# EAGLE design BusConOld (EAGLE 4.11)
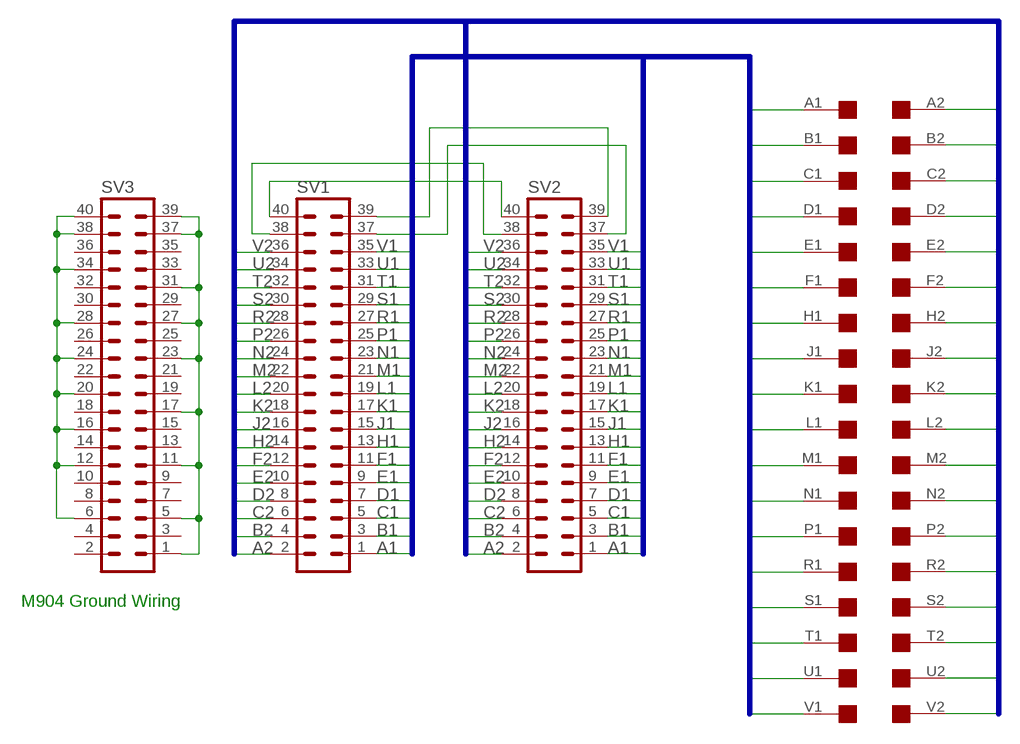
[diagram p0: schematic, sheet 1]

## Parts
SV1  MA20-2W  [MA20-2W]
SV2  MA20-2W  [MA20-2W]
SV3  MA20-2W  [MA20-2W]
U$1  DEC-FLIPCHIP  [DEC-FLIPCHIP]

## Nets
A1: SV1.1 SV2.1 U$1.A1
A2: SV1.2 SV2.2 U$1.A2
B1: SV1.3 SV2.3 U$1.B1
B2: SV1.4 SV2.4 U$1.B2
C1: SV1.5 SV2.5 U$1.C1
C2: SV1.6 SV2.6 U$1.C2
D1: SV1.7 SV2.7 U$1.D1
D2: SV1.8 SV2.8 U$1.D2
E1: SV1.9 SV2.9 U$1.E1
E2: SV1.10 SV2.10 U$1.E2
F1: SV1.11 SV2.11 U$1.F1
F2: SV1.12 SV2.12 U$1.F2
H1: SV1.13 SV2.13 U$1.H1
H2: SV1.14 SV2.14 U$1.H2
J1: SV1.15 SV2.15 U$1.J1
J2: SV1.16 SV2.16 U$1.J2
K1: SV1.17 SV2.17 U$1.K1
K2: SV1.18 SV2.18 U$1.K2
L1: SV1.19 SV2.19 U$1.L1
L2: SV1.20 SV2.20 U$1.L2
M1: SV1.21 SV2.21 U$1.M1
M2: SV1.22 SV2.22 U$1.M2
N1: SV1.23 SV2.23 U$1.N1
N2: SV1.24 SV2.24 U$1.N2
N$1: SV1.40 SV2.40
N$2: SV1.38 SV2.38
N$3: SV1.37 SV2.37
N$4: SV1.39 SV2.39
N$5: SV3.1 SV3.5 SV3.11 SV3.17 SV3.23 SV3.27 SV3.31 SV3.37 SV3.39
N$6: SV3.6 SV3.12 SV3.16 SV3.20 SV3.24 SV3.28 SV3.34 SV3.38 SV3.40
P1: SV1.25 SV2.25 U$1.P1
P2: SV1.26 SV2.26 U$1.P2
R1: SV1.27 SV2.27 U$1.R1
R2: SV1.28 SV2.28 U$1.R2
S1: SV1.29 SV2.29 U$1.S1
S2: SV1.30 SV2.30 U$1.S2
T1: SV1.31 SV2.31 U$1.T1
T2: SV1.32 SV2.32 U$1.T2
U1: SV1.33 SV2.33 U$1.U1
U2: SV1.34 SV2.34 U$1.U2
V1: SV1.35 SV2.35 U$1.V1
V2: SV1.36 SV2.36 U$1.V2
Unconnected: SV3.2 SV3.3 SV3.4 SV3.7 SV3.8 SV3.9 SV3.10 SV3.13 SV3.14 SV3.15 SV3.18 SV3.19 SV3.21 SV3.22 SV3.25 SV3.26 SV3.29 SV3.30 SV3.32 SV3.33 SV3.35 SV3.36

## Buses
A1,B1,C1,D1,E1,F1,H1,J1,K1,L1,M1,N1,P1,R1,S1,T1,U1,V1
A2,B2,C2,D2,E2,F2,H2,J2,K2,L2,M2,N2,P2,R2,S2,T2,U2,V2

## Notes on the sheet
- M904 Ground Wiring

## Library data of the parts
SV1-SV3 = con-lstb:MA20-2W: PIN HEADER
U$1 = con-dec:DEC-FLIPCHIP: DEC Flip-Chip single card fingers

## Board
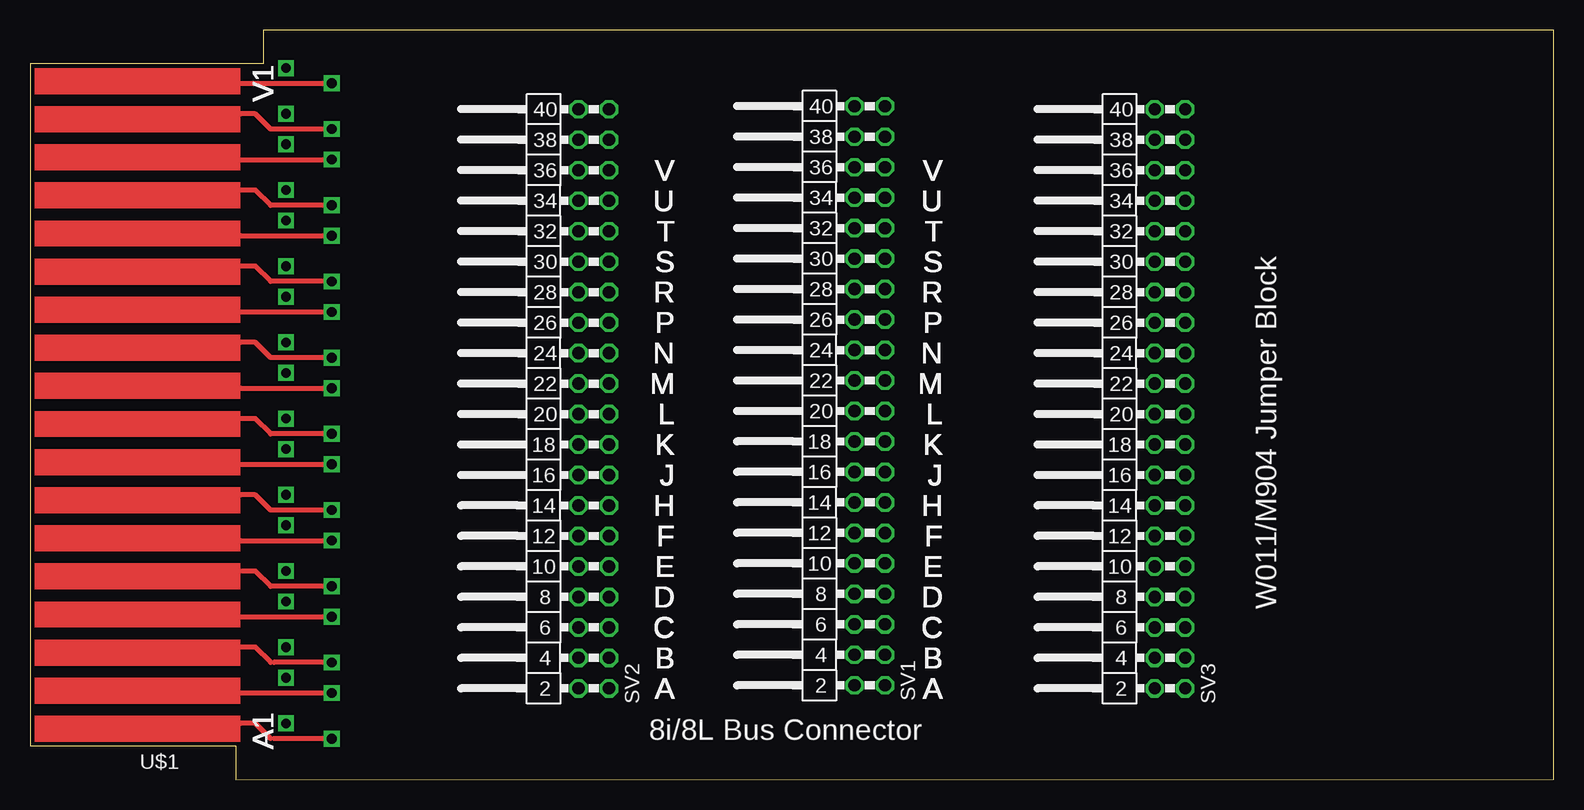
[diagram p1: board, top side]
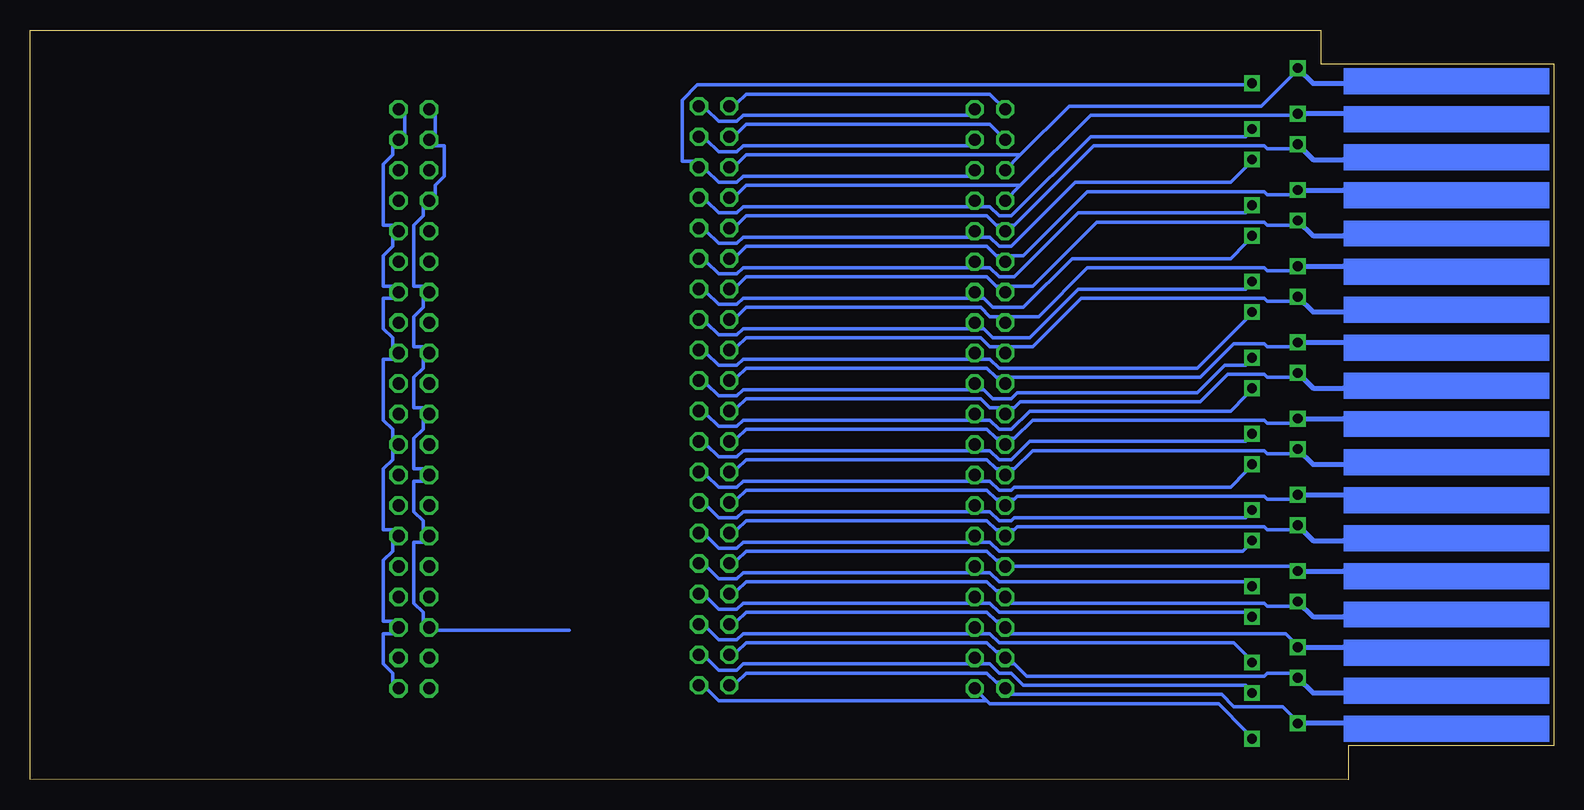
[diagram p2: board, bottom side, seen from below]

Size 126.98 x 62.48 mm. Coordinates in mm from the lower left corner, seen from the top.
Outline: 0,2.83 17.14,2.83 17.14,0 126.98,0.04 126.98,62.45 19.43,62.48 19.43,59.65 0,59.65 0,2.83
Copper layers (1*16): Top 0.035mm / dielectric 1.5mm / Bottom 0.035mm
Design rules "10mils": minimum track width 12mil, minimum drill 28mil, track to track 10mil, track to pad 10mil, pad to pad 10mil, via to via 10mil, smd to smd 10mil, copper to edge 40mil, drill to drill 10mil, minimum pad ring 10mil, minimum via ring 8mil, stop-mask expansion 0mil, vias tented up to drill 0mil, thermal gap 10mil

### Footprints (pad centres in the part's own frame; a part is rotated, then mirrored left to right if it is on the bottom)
MA20-2W = drill 1.016 octagon: 1 -24.13,-1.27; 2 -24.13,1.27; 3 -21.59,-1.27; 4 -21.59,1.27; 5 -19.05,-1.27; 6 -19.05,1.27; 7 -16.51,-1.27; 8 -16.51,1.27; 9 -13.97,-1.27; 10 -13.97,1.27; 11 -11.43,-1.27; 12 -11.43,1.27; 13 -8.89,-1.27; 14 -8.89,1.27; 15 -6.35,-1.27; 16 -6.35,1.27; 17 -3.81,-1.27; 18 -3.81,1.27; 19 -1.27,-1.27; 20 -1.27,1.27; 21 1.27,-1.27; 22 1.27,1.27; 23 3.81,-1.27; 24 3.81,1.27; 25 6.35,-1.27; 26 6.35,1.27; 27 8.89,-1.27; 28 8.89,1.27; 29 11.43,-1.27; 30 11.43,1.27; 31 13.97,-1.27; 32 13.97,1.27; 33 16.51,-1.27; 34 16.51,1.27; 35 19.05,-1.27; 36 19.05,1.27; 37 21.59,-1.27; 38 21.59,1.27; 39 24.13,-1.27; 40 24.13,1.27
DEC-FLIPCHIP = drill 0.813 square: A1 -7.62,27.94; A2 -3.81,26.67; B1 -7.62,24.13; B2 -3.81,22.86; C1 -7.62,21.59; C2 -3.81,20.32; D1 -7.62,17.78; D2 -3.81,16.51; E1 -7.62,15.24; E2 -3.81,13.97; F1 -7.62,11.43; F2 -3.81,10.16; H1 -7.62,8.89; H2 -3.81,7.62; J1 -7.62,5.08; J2 -3.81,3.81; K1 -7.62,2.54; K2 -3.81,1.27; L1 -7.62,-1.27; L2 -3.81,-2.54; M1 -7.62,-3.81; M2 -3.81,-5.08; N1 -7.62,-7.62; N2 -3.81,-8.89; P1 -7.62,-10.16; P2 -3.81,-11.43; R1 -7.62,-13.97; R2 -3.81,-15.24; S1 -7.62,-16.51; S2 -3.81,-17.78; T1 -7.62,-20.32; T2 -3.81,-21.59; U1 -7.62,-22.86; U2 -3.81,-24.13; V1 -7.62,-26.67; V2 -3.81,-27.94

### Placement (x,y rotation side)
SV1  69.97,32 90 top
SV2  46.98,31.75 90 top
SV3  94.99,31.75 90 top
U$1  17.52,31.37 180 top

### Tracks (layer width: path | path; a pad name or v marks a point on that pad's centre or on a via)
A1
  Bottom 0.305: 47.24,6.6 46.98,6.35 27.94,6.35 25.65,4.06 U$1.A1 | 47.24,6.6 SV2.1 | 47.24,6.6 69.59,6.6 70.61,7.62 SV1.1
A2
  Bottom 0.305: U$1.A2 21.84,5.33 22.6,6.1 26.67,6.1 27.68,7.11 45.21,7.11 SV2.2 46.22,8.13 46.48,8.13 47.24,8.89 67.31,8.89 68.07,8.13 SV1.2
B1
  Bottom 0.305: U$1.B1 25.65,7.87 44.19,7.87 45.21,8.89 46.22,8.89 46.98,9.65 47.75,9.65 SV2.3 48.76,9.65 67.56,9.65 68.07,9.14 69.59,9.14 70.61,10.16 SV1.3
B2
  Bottom 0.305: U$1.B2 21.84,8.89 23.87,8.89 24.12,8.64 43.94,8.64 44.95,9.65 45.21,9.65 SV2.4 46.22,10.67 46.48,10.67 47.24,11.43 67.31,11.43 68.07,10.67 SV1.4
C1
  Bottom 0.305: U$1.C1 25.65,10.41 26.67,11.43 46.22,11.43 46.98,12.19 47.75,12.19 SV2.5 48.76,12.19 67.56,12.19 68.07,11.68 69.59,11.68 70.61,12.7 SV1.5
C2
  Bottom 0.305: U$1.C2 21.84,11.68 22.35,12.19 45.21,12.19 SV2.6 46.22,13.21 46.48,13.21 47.24,13.97 67.31,13.97 68.07,13.21 SV1.6
D1
  Bottom 0.305: U$1.D1 25.65,13.97 46.22,13.97 46.98,14.73 47.75,14.73 SV2.7 48.76,14.73 67.56,14.73 68.07,14.22 69.59,14.22 70.61,15.24 SV1.7
D2
  Bottom 0.305: U$1.D2 21.84,14.48 23.87,14.48 24.12,14.73 45.21,14.73 SV2.8 46.22,15.75 46.48,15.75 47.24,16.51 67.31,16.51 68.07,15.75 SV1.8
E1
  Bottom 0.305: U$1.E1 25.65,16.51 46.22,16.51 46.98,17.27 47.75,17.27 SV2.9 48.76,17.27 67.56,17.27 68.07,16.76 69.59,16.76 70.61,17.78 SV1.9
E2
  Bottom 0.305: U$1.E2 21.84,17.78 SV2.10 46.22,18.29 46.48,18.29 47.24,19.05 67.31,19.05 68.07,18.29 SV1.10
F1
  Bottom 0.305: U$1.F1 25.65,19.3 25.9,19.05 46.22,19.05 46.98,19.81 47.75,19.81 SV2.11 48.76,19.81 67.56,19.81 68.07,19.3 69.59,19.3 70.61,20.32 SV1.11
F2
  Bottom 0.305: U$1.F2 21.84,20.83 23.87,20.83 24.12,21.08 44.7,21.08 44.95,20.83 45.21,20.83 SV2.12 46.22,20.83 46.48,20.83 47.24,21.59 67.31,21.59 68.07,20.83 SV1.12
H1
  Bottom 0.305: U$1.H1 25.65,21.84 44.95,21.84 45.21,21.59 46.22,21.59 46.98,22.35 47.75,22.35 SV2.13 48.76,22.35 67.56,22.35 68.07,21.84 69.59,21.84 70.61,22.86 SV1.13
H2
  Bottom 0.305: U$1.H2 21.84,23.37 23.87,23.37 24.12,23.62 44.7,23.62 44.95,23.37 45.21,23.37 SV2.14 46.22,23.37 46.48,23.37 47.24,24.13 67.31,24.13 68.07,23.37 SV1.14
J1
  Bottom 0.305: U$1.J1 25.65,25.65 26.92,24.38 44.95,24.38 45.21,24.13 46.22,24.13 46.98,24.89 47.75,24.89 SV2.15 48.76,24.89 67.56,24.89 68.07,24.38 69.59,24.38 70.61,25.4 SV1.15
J2
  Bottom 0.305: U$1.J2 21.84,27.18 23.87,27.18 24.12,27.43 43.43,27.43 44.95,25.91 45.21,25.91 SV2.16 46.22,25.91 46.48,25.91 47.24,26.67 67.31,26.67 68.07,25.91 SV1.16
K1
  Bottom 0.305: U$1.K1 25.65,28.19 43.68,28.19 45.21,26.67 46.22,26.67 46.98,27.43 47.75,27.43 SV2.17 48.76,27.43 67.56,27.43 68.07,26.92 69.59,26.92 70.61,27.94 SV1.17
K2
  Bottom 0.305: U$1.K2 21.84,29.72 23.87,29.72 24.12,29.97 43.43,29.97 44.95,28.45 45.21,28.45 SV2.18 46.22,28.45 46.48,28.45 47.24,29.21 67.31,29.21 68.07,28.45 SV1.18
L1
  Bottom 0.305: U$1.L1 25.65,32 26.92,30.73 43.68,30.73 45.21,29.21 46.22,29.21 46.98,29.97 47.75,29.97 SV2.19 48.76,29.97 67.56,29.97 68.07,29.46 69.59,29.46 70.61,30.48 SV1.19
L2
  Bottom 0.305: SV1.20 68.07,30.99 67.31,31.75 47.75,31.75 46.98,30.99 46.22,30.99 SV2.20 45.21,30.99 44.95,30.99 44.45,31.5 29.46,31.5 27.17,33.78 24.12,33.78 23.87,33.53 21.84,33.53 U$1.L2
M1
  Bottom 0.305: SV1.21 70.61,33.02 69.59,32 68.07,32 67.56,32.51 48.76,32.51 SV2.21 47.75,32.51 47.49,32.51 46.73,31.75 45.21,31.75 44.7,32.26 29.71,32.26 27.43,34.54 25.65,34.54 U$1.M1
M2
  Bottom 0.305: SV1.22 68.07,33.53 67.31,34.29 47.24,34.29 46.48,33.53 46.22,33.53 SV2.22 45.21,33.53 29.46,33.53 26.67,36.32 24.12,36.32 23.87,36.07 21.84,36.07 U$1.M2
N1
  Bottom 0.305: SV1.23 70.61,35.56 69.59,34.54 68.07,34.54 67.56,35.05 48.76,35.05 SV2.23 47.75,35.05 46.98,35.05 46.22,34.29 29.71,34.29 25.65,38.35 U$1.N1
N2
  Bottom 0.305: SV1.24 68.07,36.07 67.31,36.83 47.75,36.83 46.98,36.07 46.22,36.07 SV2.24 45.21,36.07 43.43,36.07 39.36,40.13 24.12,40.13 23.87,39.88 21.84,39.88 U$1.N2
N$1
  Bottom 0.305: SV2.40 46.98,57.15 67.31,57.15 68.07,56.39 SV1.40
N$2
  Bottom 0.305: SV2.38 46.98,54.61 67.31,54.61 68.07,53.85 SV1.38
N$3
  Bottom 0.305: SV2.37 48.76,52.83 67.56,52.83 68.07,52.32 69.59,52.32 70.61,53.34 SV1.37
N$4
  Bottom 0.305: SV2.39 48.76,55.37 67.56,55.37 68.07,54.86 69.59,54.86 70.61,55.88 SV1.39
N$5
  Bottom 0.305: SV3.1 96.77,8.13 96.77,8.89 97.53,9.65 97.53,12.19 96.77,12.19 SV3.5 96.77,13.21 97.53,13.21 97.53,18.29 96.77,19.05 96.77,19.81 SV3.11 96.77,20.83 97.53,20.83 97.53,25.91 96.77,26.67 96.77,27.43 SV3.17 96.77,28.45 96.77,29.21 97.53,29.97 97.53,35.05 96.77,35.05 SV3.23 96.77,36.07 96.77,36.83 97.53,37.59 97.53,40.13 96.77,40.13 SV3.27 96.77,41.15 97.53,41.15 97.53,43.69 96.77,44.45 96.77,45.21 SV3.31 96.77,46.23 97.53,46.23 97.53,51.31 96.77,52.07 96.77,52.83 SV3.37 95.75,53.85 95.75,55.37 SV3.39
N$6
  Bottom 0.305: 82.04,12.45 93.21,12.45 SV3.6 94.23,13.21 94.23,13.97 94.99,14.73 94.99,19.81 94.23,19.81 SV3.12 94.23,20.83 94.23,21.59 94.99,22.35 94.99,24.89 94.23,24.89 SV3.16 94.23,25.91 94.99,25.91 94.99,28.45 94.23,29.21 94.23,29.97 SV3.20 94.23,30.99 94.99,30.99 94.99,33.53 94.23,34.29 94.23,35.05 SV3.24 94.23,36.07 94.99,36.07 94.99,38.61 94.23,39.37 94.23,40.13 SV3.28 94.23,41.15 94.99,41.15 94.99,46.23 94.23,46.99 94.23,47.75 SV3.34 93.21,48.77 93.21,49.53 92.45,50.29 92.45,52.83 93.21,52.83 SV3.38 93.21,53.85 93.21,55.37 SV3.40
P1
  Bottom 0.305: SV1.25 70.61,38.1 69.59,37.08 68.07,37.08 67.56,37.59 48.76,37.59 SV2.25 47.75,37.59 47.49,37.59 46.73,36.83 43.68,36.83 39.62,40.89 25.65,40.89 U$1.P1
P2
  Bottom 0.305: SV1.26 68.07,38.61 67.31,39.37 47.75,39.37 46.98,38.61 46.22,38.61 SV2.26 45.21,38.61 42.92,38.61 38.86,42.67 24.12,42.67 23.87,42.42 21.84,42.42 U$1.P2
R1
  Bottom 0.305: SV1.27 70.61,40.64 69.59,39.62 68.07,39.62 67.56,40.13 48.76,40.13 SV2.27 47.75,40.13 47.49,40.13 46.73,39.37 44.19,39.37 40.13,43.43 26.92,43.43 25.65,44.7 U$1.R1
R2
  Bottom 0.305: U$1.R2 21.84,46.23 23.87,46.23 24.12,46.48 38.09,46.48 43.43,41.15 45.21,41.15 SV2.28 46.22,41.15 46.48,41.15 47.24,41.91 67.31,41.91 68.07,41.15 SV1.28
S1
  Bottom 0.305: SV1.29 70.61,43.18 69.59,42.16 68.07,42.16 67.56,42.67 48.76,42.67 SV2.29 47.75,42.67 46.98,42.67 46.22,41.91 44.95,41.91 39.62,47.24 25.65,47.24 U$1.S1
S2
  Bottom 0.305: U$1.S2 21.84,48.77 23.87,48.77 24.12,49.02 38.86,49.02 44.19,43.69 45.21,43.69 SV2.30 46.22,43.69 46.48,43.69 47.24,44.45 67.31,44.45 68.07,43.69 SV1.30
T1
  Bottom 0.305: U$1.T1 25.65,51.05 26.92,49.78 39.87,49.78 45.21,44.45 46.22,44.45 46.98,45.21 47.75,45.21 SV2.31 48.76,45.21 67.56,45.21 68.07,44.7 69.59,44.7 70.61,45.72 SV1.31
T2
  Bottom 0.305: U$1.T2 21.84,52.58 23.87,52.58 24.12,52.83 38.35,52.83 44.95,46.23 45.21,46.23 SV2.32 46.22,46.23 46.48,46.23 47.24,46.99 67.31,46.99 68.07,46.23 SV1.32
U1
  Bottom 0.305: U$1.U1 25.65,53.59 38.6,53.59 45.21,46.99 46.22,46.99 46.98,47.75 47.75,47.75 SV2.33 48.76,47.75 67.56,47.75 68.07,47.24 69.59,47.24 70.61,48.26 SV1.33
U2
  Bottom 0.305: 44.45,49.53 38.6,55.37 21.84,55.37 U$1.U2 | 44.45,49.53 SV2.34 | 44.45,49.53 67.31,49.53 68.07,48.77 SV1.34
V1
  Bottom 0.305: U$1.V1 25.65,57.91 71.37,57.91 72.64,56.64 72.64,51.56 71.62,51.56 SV1.35 70.61,50.8 69.59,49.78 68.07,49.78 67.56,50.29 48.76,50.29 SV2.35
V2
  Bottom 0.305: 44.45,52.07 40.38,56.13 24.38,56.13 21.84,58.67 U$1.V2 | 44.45,52.07 SV2.36 | 44.45,52.07 67.31,52.07 68.07,51.31 SV1.36

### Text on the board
tPlace: W011/M904 Jumper Block | 8i/8L Bus Connector
tNames: V1 | V1 | V1 | V1 | V1 | V1 | V1 | V1 | V1 | V1 | V1 | V1 | V1 | V1 | V1 | V1 | V1 | V1 | V1 | V1 | V1 | V1 | V1 | V1 | V1 | V1 | V1 | V1 | V1 | V1 | V1 | V1 | V | V | V | V | V | V | V | V | V | V | V | V | V | V | V | V | V | V | V | V | V | V | V | V | V | V | V | V | V | V | V | V | V | V | V | V | V | V | V | V | V | V | V | V | V | V | V | V | V | V | V | V | V | V | V | V | V | V | V | V | V | V | V | V | U | U | U | U | U | U | U | U | U | U | U | U | U | U | U | U | U | U | U | U | U | U | U | U | U | U | U | U | U | U | U | U | U | U | U | U | U | U | U | U | U | U | U | U | U | U | U | U | U | U | U | U | U | U | U | U | U | U | U | U | U | U | U | U | T | T | T | T | T | T | T | T | T | T | T | T | T | T | T | T | T | T | T | T | T | T | T | T | T | T | T | T | T | T | T | T | T | T | T | T | T | T | T | T | T | T | T | T | T | T | T | T | T | T | T | T | T | T | T | T | T | T | T | T | T | T | T | T | S | S | S | S | S | S | S | S | S | S | S | S | S | S | S | S | S | S | S | S | S | S | S | S | S | S | S | S | S | S | S | S | S | S | S | S | S | S | S | S | S | S | S | S | S | S | S | S | S | S | S | S | S | S | S | S | S | S | S | S | S | S | S | S | R | R | R | R | R | R | R | R | R | R | R | R | R | R | R | R | R | R | R | R | R | R | R | R | R | R | R | R | R | R | R | R | R | R | R | R | R | R | R | R | R | R | R | R | R | R | R | R | R | R | R | R | R | R | R | R | R | R | R | R | R | R | R | R | P | P | P | P | P | P | P | P | P | P | P | P | P | P | P | P | P | P | P | P | P | P | P | P | P | P | P | P | P | P | P | P | P | P | P | P | P | P | P | P | P | P | P | P | P | P | P | P | P | P | P | P | P | P | P | P | P | P | P | P | P | P | P | P | N | N | N | N | N | N | N | N | N | N | N | N | N | N | N | N | N | N | N | N | N | N | N | N | N | N | N | N | N | N | N | N | N | N | N | N | N | N | N | N | N | N | N | N | N | N | N | N | N | N | N | N | N | N | N | N | N | N | N | N | N | N | N | N | M | M | M | M | M | M | M | M | M | M | M | M | M | M | M | M | M | M | M | M | M | M | M | M | M | M | M | M | M | M | M | M | M | M | M | M | M | M | M | M | M | M | M | M | M | M | M | M | M | M | M | M | M | M | M | M | M | M | M | M | M | M | M | M | L | L | L | L | L | L | L | L | L | L | L | L | L | L | L | L | L | L | L | L | L | L | L | L | L | L | L | L | L | L | L | L | L | L | L | L | L | L | L | L | L | L | L | L | L | L | L | L | L | L | L | L | L | L | L | L | L | L | L | L | L | L | L | L | K | K | K | K | K | K | K | K | K | K | K | K | K | K | K | K | K | K | K | K | K | K | K | K | K | K | K | K | K | K | K | K | K | K | K | K | K | K | K | K | K | K | K | K | K | K | K | K | K | K | K | K | K | K | K | K | K | K | K | K | K | K | K | K | J | J | J | J | J | J | J | J | J | J | J | J | J | J | J | J | J | J | J | J | J | J | J | J | J | J | J | J | J | J | J | J | J | J | J | J | J | J | J | J | J | J | J | J | J | J | J | J | J | J | J | J | J | J | J | J | J | J | J | J | J | J | J | J | H | H | H | H | H | H | H | H | H | H | H | H | H | H | H | H | H | H | H | H | H | H | H | H | H | H | H | H | H | H | H | H | H | H | H | H | H | H | H | H | H | H | H | H | H | H | H | H | H | H | H | H | H | H | H | H | H | H | H | H | H | H | H | H | F | F | F | F | F | F | F | F | F | F | F | F | F | F | F | F | F | F | F | F | F | F | F | F | F | F | F | F | F | F | F | F | F | F | F | F | F | F | F | F | F | F | F | F | F | F | F | F | F | F | F | F | F | F | F | F | F | F | F | F | F | F | F | F | E | E | E | E | E | E | E | E | E | E | E | E | E | E | E | E | E | E | E | E | E | E | E | E | E | E | E | E | E | E | E | E | E | E | E | E | E | E | E | E | E | E | E | E | E | E | E | E | E | E | E | E | E | E | E | E | E | E | E | E | E | E | E | E | D | D | D | D | D | D | D | D | D | D | D | D | D | D | D | D | D | D | D | D | D | D | D | D | D | D | D | D | D | D | D | D | D | D | D | D | D | D | D | D | D | D | D | D | D | D | D | D | D | D | D | D | D | D | D | D | D | D | D | D | D | D | D | D | C | C | C | C | C | C | C | C | C | C | C | C | C | C | C | C | C | C | C | C | C | C | C | C | C | C | C | C | C | C | C | C | C | C | C | C | C | C | C | C | C | C | C | C | C | C | C | C | C | C | C | C | C | C | C | C | C | C | C | C | C | C | C | C | B | B | B | B | B | B | B | B | B | B | B | B | B | B | B | B | B | B | B | B | B | B | B | B | B | B | B | B | B | B | B | B | B | B | B | B | B | B | B | B | B | B | B | B | B | B | B | B | B | B | B | B | B | B | B | B | B | B | B | B | B | B | B | B | A | A | A | A | A | A | A | A | A | A | A | A | A | A | A | A | A | A | A | A | A | A | A | A | A | A | A | A | A | A | A | A | A | A | A | A | A | A | A | A | A | A | A | A | A | A | A | A | A | A | A | A | A | A | A | A | A | A | A | A | A | A | A | A | A1 | A1 | A1 | A1 | A1 | A1 | A1 | A1 | A1 | A1 | A1 | A1 | A1 | A1 | A1 | A1 | A1 | A1 | A1 | A1 | A1 | A1 | A1 | A1 | A1 | A1 | A1 | A1 | A1 | A1 | A1 | A1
